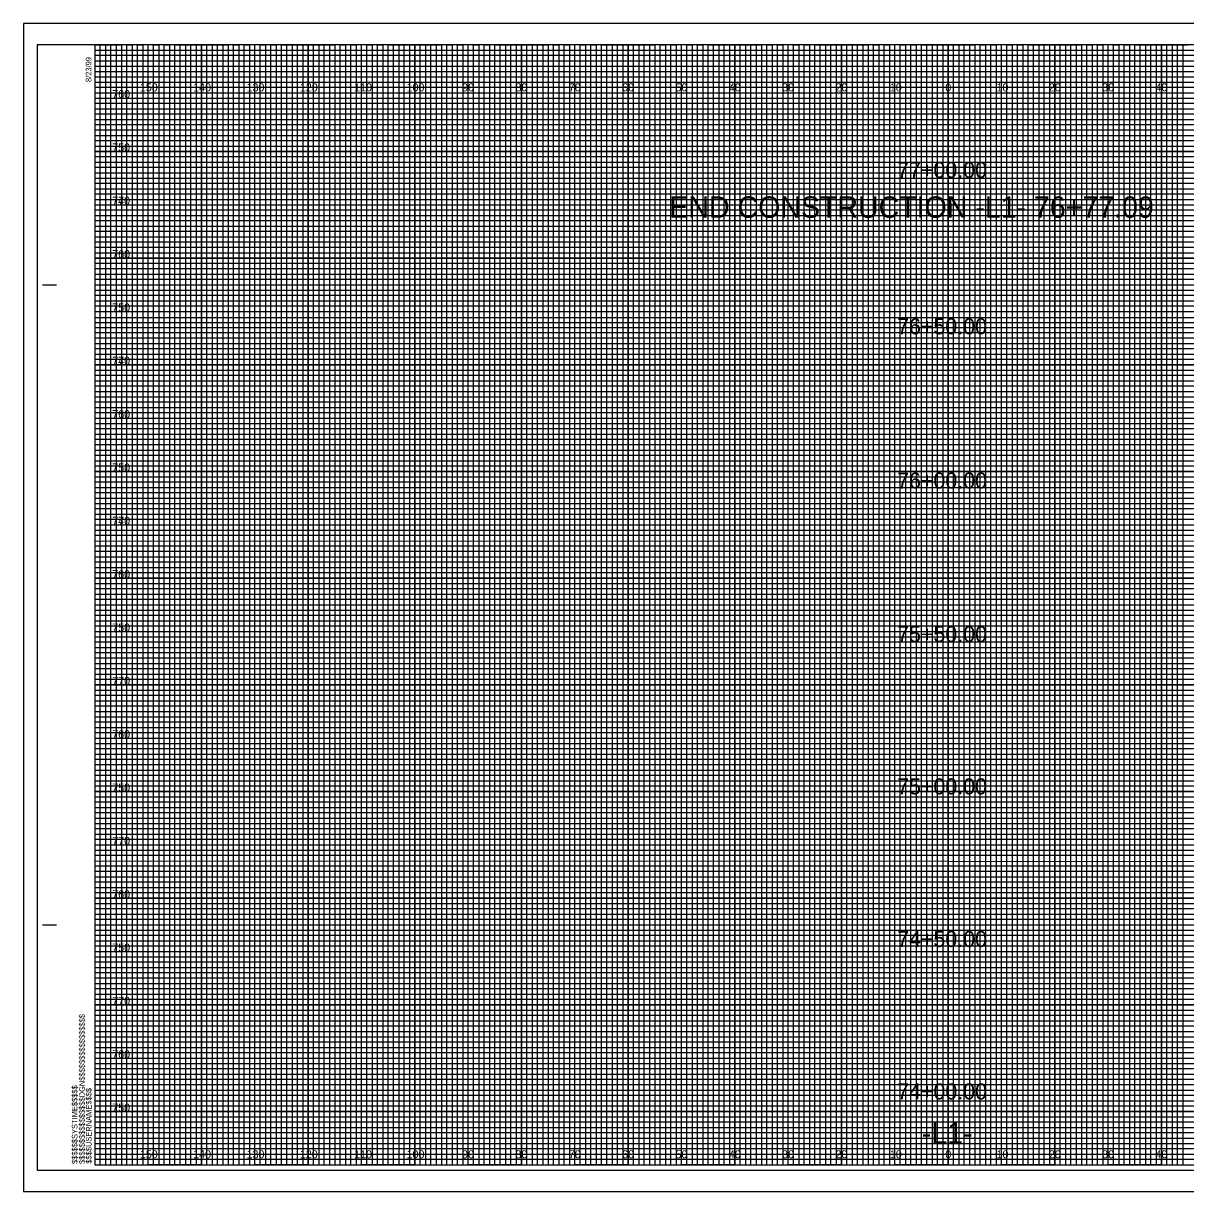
# Model space of a CAD drawing. Extents: x -13 to 323, y 2195 to 2414.
# Drawn here: x -13.4 to 204.5, y 2195 to 2414 of the extents above; entities that cross this region are included whole.
import ezdxf

# ---------------------------------------------------------------- set-up
doc = ezdxf.new("R2010")
doc.units = 0
for name, color, linetype in [('Exist Cross Section Cell', 7, 'Continuous'), ('Exist XS Center Line Elevation Label', 7, 'Continuous'), ('Exist XS Ground Line', 7, 'Continuous'), ('Prop XS Ditch Slope Text', 7, 'Continuous'), ('Prop XS Ditch Standard Text', 7, 'Continuous'), ('Prop XS Dump Level', 7, 'Continuous'), ('Prop XS Finish Grade', 7, 'Continuous'), ('Prop XS Finish Grade Earthwork', 7, 'Continuous'), ('Prop XS Finish Grade Paved Shoulder', 7, 'Continuous'), ('Prop XS Hydro Typical Ditch Data', 7, 'Continuous'), ('Prop XS Pvmt Edge Slope', 7, 'Continuous'), ('Prop XS Side Slope Text', 7, 'Continuous'), ('Prop XS Subgrade Earthwork', 7, 'Continuous')]:
    doc.layers.add(name, color=color, linetype=linetype)

msp = doc.modelspace()

# ---------------------------------------------------------------- linework, layer by layer
at = {"layer": 'Exist XS Center Line Elevation Label'}
for points in [[(0, 2410), (5, 2410), (5, 2200), (15, 2200), (15, 2410), (25, 2410), (25, 2200), (35, 2200), (35, 2410), (45, 2410), (45, 2200), (55, 2200), (55, 2410), (65, 2410), (65, 2200), (75, 2200), (75, 2410), (85, 2410), (85, 2200), (95, 2200), (95, 2410), (105, 2410), (105, 2200), (115, 2200), (115, 2410), (125, 2410), (125, 2200), (135, 2200), (135, 2410), (145, 2410), (145, 2200), (155, 2200), (155, 2410), (165, 2410), (165, 2200), (175, 2200), (175, 2410), (185, 2410), (185, 2200), (195, 2200), (195, 2410), (205, 2410)], [(0, 2405), (275, 2405)], [(0, 2385), (320, 2385), (320, 2395), (0, 2395)], [(0, 2365), (320, 2365), (320, 2375), (0, 2375)], [(0, 2345), (320, 2345), (320, 2355), (0, 2355)], [(0, 2325), (320, 2325), (320, 2335), (0, 2335)], [(0, 2305), (320, 2305), (320, 2315), (0, 2315)], [(0, 2285), (320, 2285), (320, 2295), (0, 2295)], [(0, 2265), (320, 2265), (320, 2275), (0, 2275)], [(0, 2245), (320, 2245), (320, 2255), (0, 2255)], [(0, 2225), (320, 2225), (320, 2235), (0, 2235)], [(0, 2205), (320, 2205), (320, 2215), (0, 2215)]]:
    msp.add_lwpolyline(points, dxfattribs=at)
at = {"layer": 'Exist XS Ground Line'}
for p, q in [((10, 2410), (0, 2410)), ((10, 2200), (10, 2410)), ((30, 2410), (20, 2410)), ((20, 2410), (20, 2200)), ((30, 2200), (30, 2410)), ((50, 2410), (40, 2410)), ((40, 2410), (40, 2200)), ((50, 2200), (50, 2410)), ((70, 2410), (60, 2410)), ((60, 2410), (60, 2200)), ((70, 2200), (70, 2410)), ((90, 2410), (80, 2410)), ((80, 2410), (80, 2200)), ((90, 2200), (90, 2410)), ((110, 2410), (100, 2410)), ((100, 2410), (100, 2200)), ((110, 2200), (110, 2410)), ((130, 2410), (120, 2410)), ((120, 2410), (120, 2200)), ((130, 2200), (130, 2410)), ((150, 2410), (140, 2410)), ((140, 2410), (140, 2200)), ((150, 2200), (150, 2410)), ((170, 2410), (160, 2410)), ((160, 2410), (160, 2200)), ((170, 2200), (170, 2410)), ((190, 2410), (180, 2410)), ((180, 2410), (180, 2200)), ((190, 2200), (190, 2410)), ((210, 2410), (200, 2410)), ((200, 2410), (200, 2200)), ((20, 2200), (10, 2200)), ((40, 2200), (30, 2200)), ((60, 2200), (50, 2200)), ((80, 2200), (70, 2200)), ((100, 2200), (90, 2200)), ((120, 2200), (110, 2200)), ((140, 2200), (130, 2200)), ((160, 2200), (150, 2200)), ((180, 2200), (170, 2200)), ((200, 2200), (190, 2200))]:
    msp.add_line(p, q, dxfattribs=at)
for points in [[(0, 2400), (320, 2400), (320, 2390), (0, 2390)], [(0, 2380), (320, 2380), (320, 2370), (0, 2370)], [(0, 2360), (320, 2360), (320, 2350), (0, 2350)], [(0, 2340), (320, 2340), (320, 2330), (0, 2330)], [(0, 2320), (320, 2320), (320, 2310), (0, 2310)], [(0, 2300), (320, 2300), (320, 2290), (0, 2290)], [(0, 2280), (320, 2280), (320, 2270), (0, 2270)], [(0, 2260), (320, 2260), (320, 2250), (0, 2250)], [(0, 2240), (320, 2240), (320, 2230), (0, 2230)], [(0, 2220), (320, 2220), (320, 2210), (0, 2210)]]:
    msp.add_lwpolyline(points, dxfattribs=at)
at = {"layer": 'Prop XS Ditch Slope Text'}
for points in [[(0, 2200), (1, 2200), (1, 2410), (2, 2410), (2, 2200)], [(2, 2200), (3, 2200), (3, 2410), (4, 2410), (4, 2200)], [(5, 2200), (6, 2200), (6, 2410), (7, 2410), (7, 2200)], [(7, 2200), (8, 2200), (8, 2410), (9, 2410), (9, 2200)], [(10, 2200), (11, 2200), (11, 2410), (12, 2410), (12, 2200)], [(12, 2200), (13, 2200), (13, 2410), (14, 2410), (14, 2200)], [(15, 2200), (16, 2200), (16, 2410), (17, 2410), (17, 2200)], [(17, 2200), (18, 2200), (18, 2410), (19, 2410), (19, 2200)], [(20, 2200), (21, 2200), (21, 2410), (22, 2410), (22, 2200)], [(22, 2200), (23, 2200), (23, 2410), (24, 2410), (24, 2200)], [(25, 2200), (26, 2200), (26, 2410), (27, 2410), (27, 2200)], [(27, 2200), (28, 2200), (28, 2410), (29, 2410), (29, 2200)], [(30, 2200), (31, 2200), (31, 2410), (32, 2410), (32, 2200)], [(32, 2200), (33, 2200), (33, 2410), (34, 2410), (34, 2200)], [(35, 2200), (36, 2200), (36, 2410), (37, 2410), (37, 2200)], [(37, 2200), (38, 2200), (38, 2410), (39, 2410), (39, 2200)], [(40, 2200), (41, 2200), (41, 2410), (42, 2410), (42, 2200)], [(42, 2200), (43, 2200), (43, 2410), (44, 2410), (44, 2200)], [(45, 2200), (46, 2200), (46, 2410), (47, 2410), (47, 2200)], [(47, 2200), (48, 2200), (48, 2410), (49, 2410), (49, 2200)], [(50, 2200), (51, 2200), (51, 2410), (52, 2410), (52, 2200)], [(52, 2200), (53, 2200), (53, 2410), (54, 2410), (54, 2200)], [(55, 2200), (56, 2200), (56, 2410), (57, 2410), (57, 2200)], [(57, 2200), (58, 2200), (58, 2410), (59, 2410), (59, 2200)], [(60, 2200), (61, 2200), (61, 2410), (62, 2410), (62, 2200)], [(62, 2200), (63, 2200), (63, 2410), (64, 2410), (64, 2200)], [(65, 2200), (66, 2200), (66, 2410), (67, 2410), (67, 2200)], [(67, 2200), (68, 2200), (68, 2410), (69, 2410), (69, 2200)], [(70, 2200), (71, 2200), (71, 2410), (72, 2410), (72, 2200)], [(72, 2200), (73, 2200), (73, 2410), (74, 2410), (74, 2200)], [(75, 2200), (76, 2200), (76, 2410), (77, 2410), (77, 2200)], [(77, 2200), (78, 2200), (78, 2410), (79, 2410), (79, 2200)], [(80, 2200), (81, 2200), (81, 2410), (82, 2410), (82, 2200)], [(82, 2200), (83, 2200), (83, 2410), (84, 2410), (84, 2200)], [(85, 2200), (86, 2200), (86, 2410), (87, 2410), (87, 2200)], [(87, 2200), (88, 2200), (88, 2410), (89, 2410), (89, 2200)], [(90, 2200), (91, 2200), (91, 2410), (92, 2410), (92, 2200)], [(92, 2200), (93, 2200), (93, 2410), (94, 2410), (94, 2200)], [(95, 2200), (96, 2200), (96, 2410), (97, 2410), (97, 2200)], [(97, 2200), (98, 2200), (98, 2410), (99, 2410), (99, 2200)], [(100, 2200), (101, 2200), (101, 2410), (102, 2410), (102, 2200)], [(102, 2200), (103, 2200), (103, 2410), (104, 2410), (104, 2200)], [(105, 2200), (106, 2200), (106, 2410), (107, 2410), (107, 2200)], [(107, 2200), (108, 2200), (108, 2410), (109, 2410), (109, 2200)], [(110, 2200), (111, 2200), (111, 2410), (112, 2410), (112, 2200)], [(112, 2200), (113, 2200), (113, 2410), (114, 2410), (114, 2200)], [(115, 2200), (116, 2200), (116, 2410), (117, 2410), (117, 2200)], [(117, 2200), (118, 2200), (118, 2410), (119, 2410), (119, 2200)], [(120, 2200), (121, 2200), (121, 2410), (122, 2410), (122, 2200)], [(122, 2200), (123, 2200), (123, 2410), (124, 2410), (124, 2200)], [(125, 2200), (126, 2200), (126, 2410), (127, 2410), (127, 2200)], [(127, 2200), (128, 2200), (128, 2410), (129, 2410), (129, 2200)], [(130, 2200), (131, 2200), (131, 2410), (132, 2410), (132, 2200)], [(132, 2200), (133, 2200), (133, 2410), (134, 2410), (134, 2200)], [(135, 2200), (136, 2200), (136, 2410), (137, 2410), (137, 2200)], [(137, 2200), (138, 2200), (138, 2410), (139, 2410), (139, 2200)], [(140, 2200), (141, 2200), (141, 2410), (142, 2410), (142, 2200)], [(142, 2200), (143, 2200), (143, 2410), (144, 2410), (144, 2200)], [(145, 2200), (146, 2200), (146, 2410), (147, 2410), (147, 2200)], [(147, 2200), (148, 2200), (148, 2410), (149, 2410), (149, 2200)], [(150, 2200), (151, 2200), (151, 2410), (152, 2410), (152, 2200)], [(152, 2200), (153, 2200), (153, 2410), (154, 2410), (154, 2200)], [(155, 2200), (156, 2200), (156, 2410), (157, 2410), (157, 2200)], [(157, 2200), (158, 2200), (158, 2410), (159, 2410), (159, 2200)], [(160, 2200), (161, 2200), (161, 2410), (162, 2410), (162, 2200)], [(162, 2200), (163, 2200), (163, 2410), (164, 2410), (164, 2200)], [(165, 2200), (166, 2200), (166, 2410), (167, 2410), (167, 2200)], [(167, 2200), (168, 2200), (168, 2410), (169, 2410), (169, 2200)], [(170, 2200), (171, 2200), (171, 2410), (172, 2410), (172, 2200)], [(172, 2200), (173, 2200), (173, 2410), (174, 2410), (174, 2200)], [(175, 2200), (176, 2200), (176, 2410), (177, 2410), (177, 2200)], [(177, 2200), (178, 2200), (178, 2410), (179, 2410), (179, 2200)], [(180, 2200), (181, 2200), (181, 2410), (182, 2410), (182, 2200)], [(182, 2200), (183, 2200), (183, 2410), (184, 2410), (184, 2200)], [(185, 2200), (186, 2200), (186, 2410), (187, 2410), (187, 2200)], [(187, 2200), (188, 2200), (188, 2410), (189, 2410), (189, 2200)], [(190, 2200), (191, 2200), (191, 2410), (192, 2410), (192, 2200)], [(192, 2200), (193, 2200), (193, 2410), (194, 2410), (194, 2200)], [(195, 2200), (196, 2200), (196, 2410), (197, 2410), (197, 2200)], [(197, 2200), (198, 2200), (198, 2410), (199, 2410), (199, 2200)], [(200, 2200), (201, 2200), (201, 2410), (202, 2410), (202, 2200)], [(202, 2200), (203, 2200), (203, 2410), (204, 2410), (204, 2200)]]:
    msp.add_lwpolyline(points, dxfattribs=at)
at = {"layer": 'Prop XS Ditch Standard Text'}
for p, q in [((-9.8, 2365), (-7.3, 2365)), ((-9.7, 2365), (-7.2, 2365)), ((-9.8, 2245), (-7.3, 2245)), ((-9.7, 2245), (-7.2, 2245)), ((0, 2200), (0, 2200)), ((0, 2200), (0, 2200)), ((0, 2200), (0, 2200)), ((0, 2200), (0, 2200)), ((0, 2200), (0, 2200)), ((0, 2200), (0, 2200)), ((0, 2200), (0, 2200))]:
    msp.add_line(p, q, dxfattribs=at)
msp.add_lwpolyline([(320, 2410), (0, 2410), (0, 2200), (320, 2200)], close=True, dxfattribs=at)
at = {"layer": 'Prop XS Dump Level'}
for p, q in [((0, 2409), (260, 2409)), ((260, 2407.98), (0, 2407.98)), ((0, 2407.98), (0, 2407)), ((0, 2407), (260, 2407)), ((260, 2405.89), (0, 2405.89)), ((0, 2405.89), (0, 2404)), ((0, 2404), (320, 2404))]:
    msp.add_line(p, q, dxfattribs=at)
for points in [[(0, 2403), (270, 2403), (320, 2403), (320, 2402), (0, 2402)], [(0, 2401), (320, 2401), (320, 2399), (0, 2399)], [(0, 2398), (320, 2398), (320, 2397), (0, 2396.98)], [(0, 2396), (320, 2396), (320, 2394), (0, 2394)], [(0, 2393), (320, 2393), (320, 2392), (0, 2392)], [(0, 2391), (320, 2391), (320, 2389), (0, 2389)], [(0, 2388), (320, 2388), (320, 2387), (0, 2387)], [(0, 2386), (320, 2386), (320, 2384), (0, 2384)], [(0, 2383), (320, 2383), (320, 2382), (0, 2382)], [(0, 2381), (320, 2381), (320, 2379), (0, 2379)], [(0, 2378), (320, 2378), (320, 2377), (0, 2377)], [(0, 2376), (320, 2376), (320, 2373.95), (320, 2373), (320, 2372), (0, 2372)], [(0, 2374), (320, 2374), (320, 2373), (0, 2373)], [(0, 2371), (320, 2371), (320, 2369), (0, 2369.03)], [(0, 2369.03), (320, 2369), (320, 2368), (0, 2368)], [(0, 2367), (320, 2367), (320, 2366), (0, 2366)], [(0, 2364), (320, 2364), (320, 2363), (0, 2363)], [(0, 2362), (320, 2362), (320, 2361), (0, 2361)], [(-0.07, 2358.89), (320, 2358.89), (320, 2357.88), (-0.07, 2357.88)], [(0, 2357), (320, 2357), (320, 2356), (0, 2356)], [(0, 2354), (320, 2354), (320, 2353), (0, 2353)], [(0, 2352), (320, 2352), (320, 2351), (0, 2351)], [(0, 2349), (320, 2349), (320, 2348), (0, 2348)], [(0, 2347), (320, 2347), (320, 2346), (0, 2346)], [(0, 2344), (320, 2344), (320, 2343), (0, 2343)], [(0, 2342), (320, 2342), (320, 2341), (0, 2341)], [(0, 2339), (320, 2339), (319.99, 2337.98), (0, 2338)], [(0, 2337), (320, 2337), (320, 2336), (0, 2336)], [(0, 2334), (320, 2334), (320, 2333), (0, 2333)], [(0, 2332), (320, 2332), (320, 2331), (0, 2331)], [(0, 2329), (320, 2329), (320, 2328), (0, 2328)], [(0, 2327), (320, 2327), (320, 2326), (0, 2326)], [(0, 2324), (320, 2324), (320, 2323), (0, 2323)], [(0, 2322), (320, 2322), (320, 2321), (0, 2321)], [(0, 2319), (320, 2319), (320, 2318), (0, 2318)], [(0, 2316.99), (320.07, 2316.91), (320, 2316), (0, 2316)], [(0, 2314), (320, 2314), (320, 2313), (0, 2313)], [(0, 2312), (320, 2312), (320, 2311), (0, 2311)], [(0, 2309), (320, 2309), (320, 2308), (0, 2308)], [(0, 2307), (320, 2307), (320, 2306), (0, 2306)], [(0, 2304), (320, 2304), (320, 2303), (0, 2303)], [(0, 2302), (320, 2302), (320, 2301), (0, 2301)], [(0, 2299), (320, 2299), (320, 2298), (0, 2298)], [(0, 2297), (320, 2297), (320, 2296), (0, 2296)], [(0, 2294), (320, 2294), (320, 2293), (0, 2293)], [(0, 2292), (320, 2292), (320, 2291), (0, 2291)], [(0, 2289), (320, 2289), (320, 2288), (0, 2288)], [(0, 2287), (320, 2287), (320, 2286), (0, 2286)], [(0, 2284), (320, 2284), (320, 2283), (0, 2283)], [(0, 2282), (320, 2282), (320, 2281), (0, 2281)], [(0, 2279), (320, 2279), (319.99, 2277.98), (0, 2278)], [(0, 2277), (320, 2277), (320, 2276), (0, 2276)], [(0, 2274), (320, 2274), (320, 2273), (0, 2273)], [(0, 2272), (320, 2272), (320, 2271), (0, 2271)], [(0, 2269), (320, 2269), (320, 2268), (0, 2268)], [(0, 2267), (320, 2267), (320, 2266), (0, 2266)], [(0, 2264), (320, 2264), (320, 2263), (0, 2263)], [(0, 2262), (320, 2262), (320, 2261), (0, 2261)], [(0, 2259), (320, 2259), (320, 2258), (0, 2258)], [(0, 2256.99), (320.07, 2256.91), (320, 2256), (0, 2256)], [(0, 2254), (320, 2254), (320, 2253), (0, 2253)], [(0, 2252), (320, 2252), (320, 2251), (0, 2251)], [(0, 2249), (320, 2249), (320, 2248), (0, 2248)], [(0, 2247), (320, 2247), (320, 2246), (0, 2246)], [(0, 2244), (320, 2244), (320, 2243), (0, 2243)], [(0, 2242), (320, 2242), (320, 2241), (0, 2241)], [(0, 2239), (320, 2239), (320, 2238), (0, 2238)], [(0, 2237), (320, 2237), (320, 2236), (0, 2236)], [(0, 2234), (320, 2234), (320, 2233), (0, 2233)], [(0, 2232), (320, 2232), (320, 2231), (0, 2231)], [(0, 2229), (320, 2229), (320, 2228), (0, 2228)], [(0, 2227), (320, 2227), (320, 2226), (0, 2226)], [(0, 2224), (320, 2224), (320, 2223), (0, 2223)], [(0, 2222), (320, 2222), (320, 2221), (0, 2221)], [(0, 2219), (320, 2219), (320, 2218), (0, 2218)], [(0, 2217), (320, 2217), (320, 2216), (0, 2216)], [(0, 2214), (320, 2214), (320, 2213), (0, 2213)], [(0, 2212), (320, 2212), (320, 2211), (0, 2211)], [(0, 2209), (320, 2209), (320, 2208), (0, 2208)], [(0, 2207), (320, 2207), (320, 2206), (0, 2206)], [(0, 2204), (320, 2204), (320, 2203), (0, 2203)], [(0, 2202), (320, 2202), (320, 2201), (0, 2201)]]:
    msp.add_lwpolyline(points, dxfattribs=at)
at = {"layer": 'Prop XS Finish Grade'}
for p, q in [((10, 2200), (10, 2410)), ((20, 2200), (20, 2410)), ((30, 2200), (30, 2410)), ((40, 2200), (40, 2410)), ((50, 2200), (50, 2410)), ((60, 2200), (60, 2410)), ((70, 2200), (70, 2410)), ((80, 2200), (80, 2410)), ((90, 2200), (90, 2410)), ((100, 2200), (100, 2410)), ((110, 2200), (110, 2410)), ((120, 2200), (120, 2410)), ((130, 2200), (130, 2410)), ((140, 2200), (140, 2410)), ((150, 2200), (150, 2410)), ((160, 2200), (160, 2410)), ((170, 2200), (170, 2410)), ((180, 2200), (180, 2410)), ((190, 2200), (190, 2410)), ((200, 2200), (200, 2410)), ((0, 2400), (320, 2400)), ((0, 2390), (320, 2390)), ((0, 2380), (320, 2380)), ((0, 2370), (320, 2370)), ((0, 2360), (320, 2360)), ((0, 2350), (320, 2350)), ((0, 2340), (320, 2340)), ((0, 2330), (320, 2330)), ((0, 2320), (320, 2320)), ((0, 2310), (320, 2310)), ((0, 2300), (320, 2300)), ((0, 2290), (320, 2290)), ((0, 2280), (320, 2280)), ((0, 2270), (320, 2270)), ((0, 2260), (320, 2260)), ((0, 2250), (320, 2250)), ((0, 2240), (320, 2240)), ((0, 2230), (320, 2230)), ((0, 2220), (320, 2220)), ((0, 2210), (320, 2210))]:
    msp.add_line(p, q, dxfattribs=at)
at = {"layer": 'Prop XS Finish Grade Earthwork'}
msp.add_lwpolyline([(-10.8, 2199), (322.4, 2199), (322.4, 2410), (-10.8, 2410)], close=True, dxfattribs=at)
at = {"layer": 'Prop XS Hydro Typical Ditch Data'}
msp.add_lwpolyline([(-13.4, 2195), (323.3, 2195), (323.3, 2414), (-13.4, 2414)], close=True, dxfattribs=at)
at = {"layer": 'Prop XS Subgrade Earthwork'}
for p, q in [((323.3, 2414), (-13.4, 2414)), ((-13.4, 2414), (-13.4, 2195)), ((-13.4, 2195), (323.3, 2195))]:
    msp.add_line(p, q, dxfattribs=at)

# ---------------------------------------------------------------- texts
at = {"layer": 'Exist Cross Section Cell'}
for s, p in [('150', (8.44, 2401.25)), ('140', (18.44, 2401.25)), ('130', (28.44, 2401.25)), ('120', (38.44, 2401.25)), ('110', (48.62, 2401.25)), ('100', (58.44, 2401.25)), ('90', (68.86, 2401.25)), ('80', (78.86, 2401.25)), ('70', (88.86, 2401.25)), ('60', (98.86, 2401.25)), ('50', (108.86, 2401.25)), ('40', (118.86, 2401.25)), ('30', (128.86, 2401.25)), ('20', (138.86, 2401.25)), ('10', (149.04, 2401.25)), ('0', (159.45, 2401.25)), ('0', (159.45, 2401.25)), ('10', (169.04, 2401.25)), ('20', (178.86, 2401.25)), ('30', (188.86, 2401.25)), ('40', (198.86, 2401.25)), ('150', (8.44, 2201.25)), ('140', (18.44, 2201.25)), ('130', (28.44, 2201.25)), ('120', (38.44, 2201.25)), ('110', (48.62, 2201.25)), ('100', (58.44, 2201.25)), ('90', (68.86, 2201.25)), ('80', (78.86, 2201.25)), ('70', (88.86, 2201.25)), ('60', (98.86, 2201.25)), ('50', (108.86, 2201.25)), ('40', (118.86, 2201.25)), ('30', (128.86, 2201.25)), ('20', (138.86, 2201.25)), ('10', (149.04, 2201.25)), ('0', (159.45, 2201.25)), ('0', (159.45, 2201.25)), ('10', (169.04, 2201.25)), ('20', (178.86, 2201.25)), ('30', (188.86, 2201.25)), ('40', (198.86, 2201.25))]:
    msp.add_text(s, height=1.5, dxfattribs=at).set_placement(p)
at = {"layer": 'Prop XS Ditch Standard Text'}
for s, p in [('8/23/99', (-0.65, 2403)), ('$$$$$$$$$$$$$$$$DGN$$$$$$$$$$$$$$$$', (-1.88, 2200.18)), ('$$$$$$SYSTIME$$$$$', (-3.26, 2200.18)), ('$$$$USERNAME$$$$', (-0.62, 2200.23))]:
    msp.add_text(s, height=1.05, rotation=90, dxfattribs=at).set_placement(p)
at = {"layer": 'Prop XS Finish Grade Paved Shoulder'}
for s, p in [('760', (3.26, 2400)), ('750', (3.26, 2390)), ('770', (3.26, 2380)), ('740', (3.26, 2380)), ('760', (3.26, 2370)), ('750', (3.26, 2360)), ('770', (3.26, 2350)), ('740', (3.26, 2350)), ('760', (3.26, 2340)), ('750', (3.26, 2330)), ('770', (3.26, 2320)), ('740', (3.26, 2320)), ('760', (3.26, 2310)), ('750', (3.26, 2300)), ('770', (3.26, 2290)), ('760', (3.26, 2280)), ('750', (3.26, 2270)), ('770', (3.26, 2260)), ('760', (3.26, 2250)), ('750', (3.26, 2240)), ('770', (3.26, 2230)), ('760', (3.26, 2220)), ('750', (3.26, 2210))]:
    msp.add_text(s, height=1.5, dxfattribs=at).set_placement(p)
at = {"layer": 'Prop XS Pvmt Edge Slope'}
for s, p in [('77+00.00', (150.41, 2385.02)), ('76+50.00', (150.41, 2355.71)), ('76+00.00', (150.41, 2326.8)), ('75+50.00', (150.41, 2298.02)), ('75+00.00', (150.41, 2269.47)), ('74+50.00', (150.41, 2240.86)), ('74+00.00', (150.41, 2212.29))]:
    msp.add_text(s, height=3, dxfattribs=at).set_placement(p)
at = {"layer": 'Prop XS Side Slope Text'}
for s, p in [('END CONSTRUCTION -L1- 76+77.09', (107.72, 2377.56)), ('-L1-', (155.05, 2204))]:
    msp.add_text(s, height=4, dxfattribs=at).set_placement(p)

doc.saveas('drawing.dxf')
